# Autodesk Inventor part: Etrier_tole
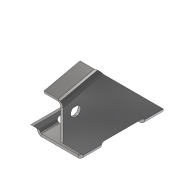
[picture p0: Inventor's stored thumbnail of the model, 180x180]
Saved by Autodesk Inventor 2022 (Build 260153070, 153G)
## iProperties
Created: 2018-06
Part Number: Etrier_tole
Material: Acier inoxydable
Document SubType Name: Tôle
Designer: Fabian Perrée
Density: 8 g/cm^3
Sheet Metal Rule: Par défaut_mm
Appearance: Semi-poli
Flat Pattern Width: 9.88042 cm
Flat Pattern Length: 9.88042 cm
Flat Pattern Area: 97.6226 cm^2
Sheet Metal Width: 98,804 mm
Sheet Metal Length: 98,804 mm
Sheet Metal Area: 9762,260 mm^2
Mass: 45.3586 g
Surface Area: 83.174 cm^2
Volume: 5.66982 cm^3
Author: Fabian Perrée
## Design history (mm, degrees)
node "Face1"
  sketch "Esquisse1"
    geometry: L1 (-12.5, 24)-(12.5, 24); L2 (12.5, 24)-(12.5, -24); L3 (12.5, -24)-(-12.5, -24); L4 (-12.5, -24)-(-12.5, 24); L5 (-12.5, 24)-(12.5, -24); L6 (12.5, 24)-(-12.5, -24); C1 r 3 at (0, 18.5); C2 r 3 at (0, -18.5); 3 further points
    constraints: 12 end point, 4 midpoint, 2 centre point, 2 parallel, 2 vertical alignment, 1 equal radius, 1 horizontal, 1 perpendicular
    dimensions: "d0" = 25 distance of L2.end L3.end; "d1" = 48 distance of L1.end L2.end; "d31" = 5.5 distance from line of L1 C1.centre (= d43); "d32" = 6 diameter of C1; "d43" = 5.5 distance from line of L3 C2.centre
node "Face2"
  sketch "Esquisse2"
    geometry: L1 (0, 0)-(0, 1.5) reference; L2 (48, 0)-(0, 0) reference; L3 (48, 0)-(48, 1.5) reference; L4 (0, 1.5)-(0, 3); L5 (0, 3)-(-12, 15); L6 (-12, 15)-(-12, 36.58); L7 (7, 3.333)-(7, -2.476); L8 (-12, 36.58)-(9.626, 41.374); L9 (48, 1.5)-(48, 3); L10 (48, 3)-(9.626, 41.374); C1 r 2.5 at (-4.5, 28); 2 further points
    constraints: 14 end point, 3 vertical, 1 centre point, 1 coincident, 1 parallel
    dimensions: "d3" = 3 distance from line of L2 L4.end; "d6" = 45 deg angle of L5 L6; "d7" = 28 distance from line of L2 point (-4.5, 28); "d8" = 7 distance between parallel lines of L4 L7; "d9" = 11.5 distance from line of point (-4.5, 28) L7; "d10" = 10 distance from line of point (-4.5, 28) L8; "d11" = 12.5 deg angle of L2 L8; "d12" = 3 distance from line of L2 L9.end; "d13" = 45 deg angle of L2 L10; "d14" = 5 diameter of C1; "d40" = 12 horizontal distance of L5.end L4.end
mirror "Symétrie1"
node "Bord tombé1"
sketch "Esquisse4"
  geometry: L1 (0, 0)-(48, 0) reference; L2 (11, 0)-(37, 0); L3 (37, 0)-(37, 2.5); L4 (35.5, 4)-(12.5, 4); L5 (11, 2.5)-(11, 0); L6 (2.5, 1.5)-(8.5, 1.5) reference; L7 (8.5, 0)-(2.5, 0) reference; L8 (0, 1.5)-(48, 1.5) reference; L9 (8.5, 0)-(2.5, 0) reference; L10 (45.5, 0)-(39.5, 0) reference; L11 (5.5, 0)-(5.5, -3.35); L12 (42.5, 0)-(42.5, -3.35); A1 r 1.5 centre (12.5, 2.5) between (12.5, 4) and (11, 2.5); A2 r 1.5 centre (35.5, 2.5) between (37, 2.5) and (35.5, 4); 3 further points
  constraints: 12 end point, 5 point on line, 4 point on circle, 4 tangent, 2 centre point, 2 midpoint, 2 parallel, 2 vertical, 1 equal radius, 1 horizontal, 1 perpendicular
  dimensions: "d35" = 1.5 radius of A1; "d36" = 4 distance between parallel lines of L2 L4; "d44" = 5.5 distance between parallel lines of L5 L11; "d45" = 5.5 distance between parallel lines of L3 L12 (= d44)
extrude "Extrusion1" cut sketch "Esquisse4" extent not by distance; stored distance "d37" = 10; taper "d38" = 0 deg
feature "Filetage1" dims "d46" = 3, "d47" = 0
sketch "Esquisse5"
  geometry: L1 (43.946, -41.715)-(6.496, -41.715); L2 (6.496, -41.715)-(6.496, 46.634); L3 (6.496, 46.634)-(43.946, 46.634); L4 (43.946, 46.634)-(43.946, -41.715); 1 further point
  constraints: 8 end point, 2 parallel, 1 horizontal, 1 perpendicular
extrude "Extrusion2" cut sketch "Esquisse5" distance "d41" = 20; taper "d42" = 0 deg
node "Solide1"
feature "Plaque1" dims "d2" = 1.5 (= Epaisseur)
feature "Plaque2" dims "d2" = 1.5 (= Epaisseur), "d15" = 1.5 (= RayonPli), "d16" = 1.5 (= LargeurGrugeage), "d18" = 3 (= RestesMinimum)
feature "Pli1" dims "d2" = 1.5 (= Epaisseur), "d15" = 1.5 (= RayonPli), "d16" = 1.5 (= LargeurGrugeage), "d17" = 0.75 (= ProfondeurGrugeage), "d18" = 3 (= RestesMinimum), "d19" = 1.5 (= Rayondetransition), "JeuJointure" = 0.01
sketch "Esquisse3"
  geometry: L1 (11.5, 0)-(11.5, 22.151); L2 (11.5, 22.151)-(0, 22.151); 1 other entity
  constraints: 4 end point, 4 other
feature "Plaque3" dims "d2" = 1.5 (= Epaisseur), "d20" = 1.5 (= LargeurGrugeage), "d21" = 0.75 (= ProfondeurGrugeage), "d22" = 3 (= RestesMinimum), "d23" = 1.5 (= Rayondetransition), "d24" = 11.5, "d25" = 90 deg, "d26" = 1.5 (= RayonPli), "d27" = 6 (= TailleGrugeage), "d28" = 1.5 (= TailleJeu), "d29" = 1.5 (= TailleRayonJacobi), "JeuJointure" = 0.01
feature "Pli2" dims "d2" = 1.5 (= Epaisseur), "d20" = 1.5 (= LargeurGrugeage), "d21" = 0.75 (= ProfondeurGrugeage), "d22" = 3 (= RestesMinimum), "d23" = 1.5 (= Rayondetransition), "d24" = 11.5, "d25" = 90 deg, "d26" = 1.5 (= RayonPli), "JeuJointure" = 0.01
feature "Coin1" dims "d24" = 11.5, "d25" = 90 deg, "d27" = 6 (= TailleGrugeage), "d28" = 1.5 (= TailleJeu), "d29" = 1.5 (= TailleRayonJacobi)
node "Boucle projetée1"
feature "Définition1"
other parameters: "Epaisseur" = 1.5 (derived), "FacteurX" = 4.4, "RayonPli" = 1.5 (= Epaisseur), "LargeurGrugeage" = 1.5 (= Epaisseur), "ProfondeurGrugeage" = 0.75 (= 0.5 x Epaisseur), "TailleGrugeage" = 6 (= 4 x Epaisseur), "RestesMinimum" = 3 (= 2 x Epaisseur), "Rayondetransition" = 1.5 (= RayonPli), "TailleRayonJacobi" = 1.5 (= RayonPli), "TailleJeu" = 1.5 (= Epaisseur), "Epaisseur" = 1.5, "LargeurGrugeage" = 1.5, "ProfondeurGrugeage" = 0.75, "RayonPli" = 1.5, "Rayondetransition" = 1.5, "RestesMinimum" = 3, "TailleGrugeage" = 6, "TailleJeu" = 1.5, "TailleRayonJacobi" = 1.5
